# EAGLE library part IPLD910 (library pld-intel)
PLD
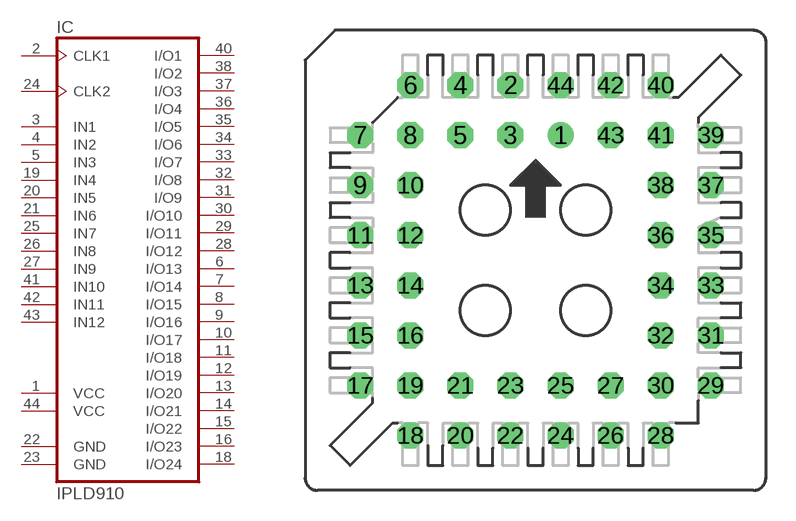
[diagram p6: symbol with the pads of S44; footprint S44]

Designator prefix IC

## IPLD910 (OC_FARNELL: unknown; OC_NEWARK: unknown)  [S44]
1  VCC  pwr
2  CLK1  in
3  IN1  in
4  IN2  in
5  IN3  in
6  I/O13
7  I/O14
8  I/O15
9  I/O16
10  I/O17
11  I/O18
12  I/O19
13  I/O20
14  I/O21
15  I/O22
16  I/O23
18  I/O24
19  IN4  in
20  IN5  in
21  IN6  in
22  GND  pwr
23  GND  pwr
24  CLK2  in
25  IN7  in
26  IN8  in
27  IN9  in
28  I/O12
29  I/O11
30  I/O10
31  I/O9
32  I/O8
33  I/O7
34  I/O6
35  I/O5
36  I/O4
37  I/O3
38  I/O2
40  I/O1
41  IN10  in
42  IN11  in
43  IN12  in
44  VCC  pwr

## Footprint S44 (pad centres in mm)
PLCC SOCKET
drill 0.813 round: 1 1.27,6.35
drill 0.813 octagon: 2 -1.27,8.89; 3 -1.27,6.35; 4 -3.81,8.89; 5 -3.81,6.35; 6 -6.35,8.89; 7 -8.89,6.35; 8 -6.35,6.35; 9 -8.89,3.81; 10 -6.35,3.81; 11 -8.89,1.27; 12 -6.35,1.27; 13 -8.89,-1.27; 14 -6.35,-1.27; 15 -8.89,-3.81; 16 -6.35,-3.81; 17 -8.89,-6.35; 18 -6.35,-8.89; 19 -6.35,-6.35; 20 -3.81,-8.89; 21 -3.81,-6.35; 22 -1.27,-8.89; 23 -1.27,-6.35; 24 1.27,-8.89; 25 1.27,-6.35; 26 3.81,-8.89; 27 3.81,-6.35; 28 6.35,-8.89; 29 8.89,-6.35; 30 6.35,-6.35; 31 8.89,-3.81; 32 6.35,-3.81; 33 8.89,-1.27; 34 6.35,-1.27; 35 8.89,1.27; 36 6.35,1.27; 37 8.89,3.81; 38 6.35,3.81; 39 8.89,6.35; 40 6.35,8.89; 41 6.35,6.35; 42 3.81,8.89; 43 3.81,6.35; 44 1.27,8.89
